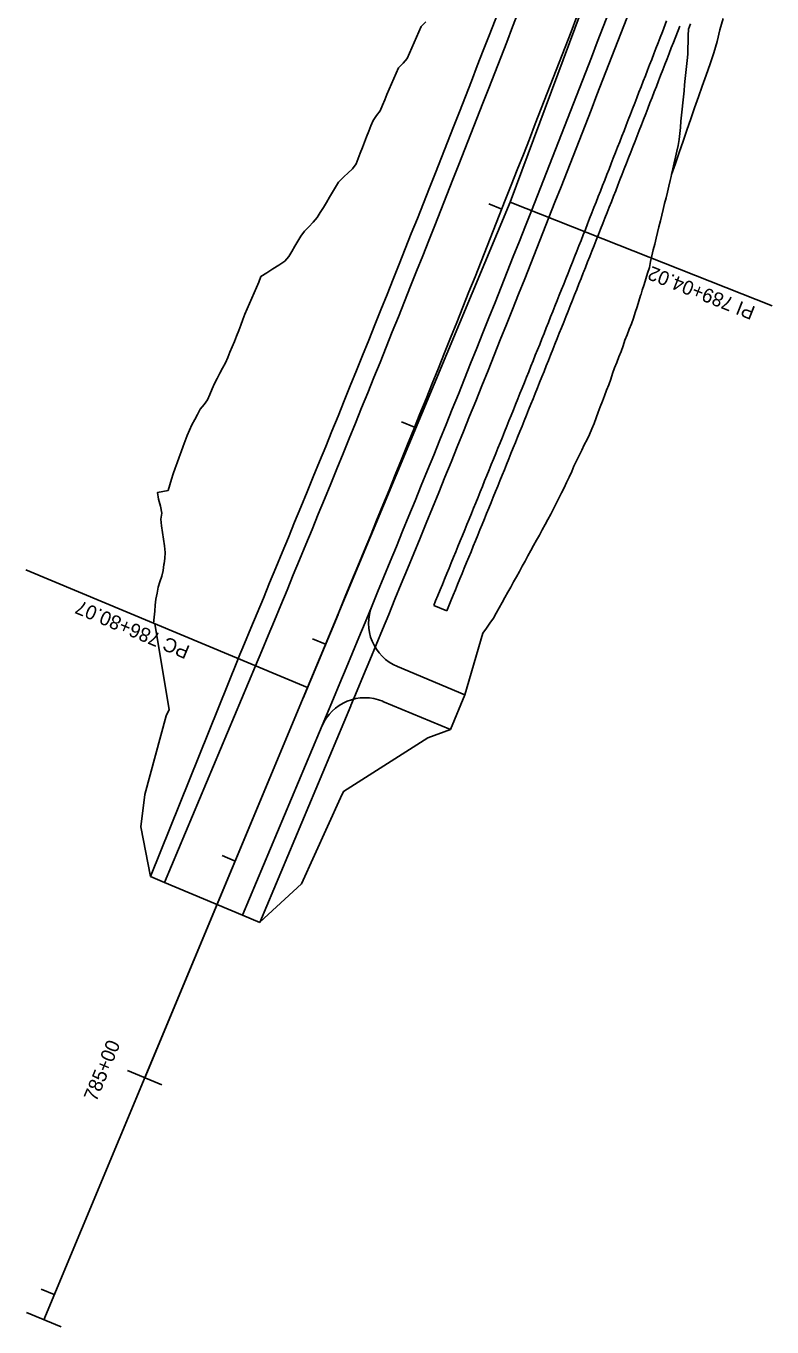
# Model space of a CAD drawing. Extents: x 1237212 to 1293764, y 379349 to 410301.
# Drawn here: x 1282908 to 1283226, y 402702 to 403256 of the extents above; entities that cross this region are included whole.
import ezdxf

# ---------------------------------------------------------------- set-up
doc = ezdxf.new("R2010")
doc.units = 0
for name, color, linetype in [('B-Sub-Footing', 7, 'Continuous'), ('B-Sub-Pier Cap', 7, 'Continuous'), ('B-Tbl-Title Block', 7, 'Continuous'), ('B-Title Block (No Plot)', 7, 'Continuous'), ('R_Exist Surface', 7, 'Continuous'), ('R_Grid', 7, 'Continuous'), ('R_Grid Annot', 7, 'Continuous'), ('R_Shld', 7, 'Continuous')]:
    doc.layers.add(name, color=color, linetype=linetype)

msp = doc.modelspace()

# ---------------------------------------------------------------- linework, layer by layer
at = {"layer": 'B-Sub-Footing'}
for p, q in [((1283066.22, 402983.18), (1283094.95, 402971.22)), ((1283038.94, 402969.6), (1283038.97, 402969.66)), ((1283060.05, 402968.41), (1283088.81, 402956.45)), ((1283094.95, 402971.22), (1283088.81, 402956.45))]:
    msp.add_line(p, q, dxfattribs=at)
for centre, start, end in [((1283073.91, 403001.64), 157.5476, 247.408), ((1283052.37, 402949.95), 67.408, 157.1925)]:
    msp.add_arc(centre, 20, start, end, dxfattribs=at)
at = {"layer": 'B-Sub-Pier Cap'}
for points in [[(1283180.92, 403258.23), (1283179.09, 403253.47), (1283178.19, 403251.13), (1283177.28, 403248.79), (1283176.38, 403246.45), (1283175.48, 403244.12), (1283174.57, 403241.78), (1283173.67, 403239.44), (1283172.76, 403237.1), (1283171.85, 403234.76), (1283170.95, 403232.42), (1283170.04, 403230.08), (1283169.13, 403227.75), (1283168.22, 403225.41), (1283167.31, 403223.07), (1283166.4, 403220.73), (1283165.5, 403218.4), (1283164.58, 403216.06), (1283163.67, 403213.72), (1283162.76, 403211.39), (1283161.85, 403209.05), (1283160.94, 403206.72), (1283160.03, 403204.38), (1283159.11, 403202.04), (1283158.2, 403199.71), (1283157.28, 403197.37), (1283156.37, 403195.04), (1283155.45, 403192.7), (1283154.54, 403190.37), (1283153.62, 403188.03), (1283152.7, 403185.7), (1283151.79, 403183.37), (1283150.87, 403181.03), (1283149.95, 403178.7), (1283149.03, 403176.36), (1283148.11, 403174.03), (1283147.19, 403171.7), (1283146.27, 403169.37), (1283145.35, 403167.03), (1283144.43, 403164.7), (1283143.5, 403162.37), (1283142.58, 403160.04), (1283141.66, 403157.7), (1283140.74, 403155.37), (1283140.05, 403153.64), (1283139.81, 403153.04), (1283138.89, 403150.71), (1283137.96, 403148.38), (1283137.04, 403146.05), (1283136.11, 403143.72), (1283135.18, 403141.39), (1283134.26, 403139.06), (1283133.33, 403136.73), (1283132.4, 403134.4), (1283131.47, 403132.07), (1283130.54, 403129.74), (1283129.61, 403127.41), (1283128.68, 403125.08), (1283127.75, 403122.75), (1283126.82, 403120.42), (1283125.89, 403118.09), (1283124.96, 403115.77), (1283124.02, 403113.44), (1283123.09, 403111.11), (1283122.16, 403108.78), (1283121.22, 403106.46), (1283120.29, 403104.13), (1283119.35, 403101.8), (1283118.42, 403099.47), (1283117.48, 403097.15), (1283116.54, 403094.82), (1283115.61, 403092.5), (1283114.67, 403090.17), (1283113.73, 403087.84), (1283112.79, 403085.52), (1283111.85, 403083.19), (1283110.91, 403080.87), (1283109.97, 403078.54), (1283109.03, 403076.22), (1283108.09, 403073.89), (1283107.15, 403071.57), (1283106.2, 403069.24), (1283105.26, 403066.92), (1283104.32, 403064.6), (1283103.37, 403062.27), (1283102.43, 403059.95), (1283101.48, 403057.63), (1283100.54, 403055.3), (1283099.59, 403052.98), (1283098.65, 403050.66), (1283097.7, 403048.34), (1283096.75, 403046.02), (1283095.8, 403043.69), (1283094.86, 403041.37), (1283093.91, 403039.05), (1283092.96, 403036.73), (1283092.01, 403034.41), (1283091.06, 403032.09), (1283090.11, 403029.77), (1283089.15, 403027.45), (1283088.2, 403025.13), (1283087.25, 403022.81), (1283086.3, 403020.49), (1283085.34, 403018.17), (1283084.39, 403015.85), (1283083.43, 403013.53), (1283082.48, 403011.21), (1283081.67, 403009.25)], [(1283087.21, 403006.94), (1283088.98, 403011.24), (1283089.94, 403013.56), (1283090.89, 403015.88), (1283091.85, 403018.21), (1283092.8, 403020.53), (1283093.75, 403022.85), (1283094.7, 403025.17), (1283095.66, 403027.49), (1283096.61, 403029.81), (1283097.56, 403032.13), (1283098.51, 403034.46), (1283099.46, 403036.78), (1283100.41, 403039.1), (1283101.36, 403041.42), (1283102.31, 403043.75), (1283103.25, 403046.07), (1283104.2, 403048.39), (1283105.15, 403050.72), (1283106.1, 403053.04), (1283107.04, 403055.37), (1283107.99, 403057.69), (1283108.93, 403060.01), (1283109.88, 403062.34), (1283110.82, 403064.66), (1283111.76, 403066.99), (1283112.71, 403069.31), (1283113.65, 403071.64), (1283114.59, 403073.97), (1283115.53, 403076.29), (1283116.47, 403078.62), (1283117.41, 403080.94), (1283118.35, 403083.27), (1283119.29, 403085.6), (1283120.23, 403087.92), (1283121.17, 403090.25), (1283122.11, 403092.58), (1283123.05, 403094.91), (1283123.98, 403097.23), (1283124.92, 403099.56), (1283125.85, 403101.89), (1283126.79, 403104.22), (1283127.72, 403106.55), (1283128.66, 403108.88), (1283129.59, 403111.21), (1283130.53, 403113.53), (1283131.46, 403115.86), (1283132.39, 403118.19), (1283133.32, 403120.52), (1283134.25, 403122.85), (1283135.18, 403125.18), (1283136.11, 403127.51), (1283137.04, 403129.84), (1283137.97, 403132.18), (1283138.9, 403134.51), (1283139.83, 403136.84), (1283140.76, 403139.17), (1283141.69, 403141.5), (1283142.61, 403143.83), (1283143.54, 403146.17), (1283144.46, 403148.5), (1283145.39, 403150.83), (1283145.63, 403151.43), (1283146.31, 403153.16), (1283147.24, 403155.5), (1283148.16, 403157.83), (1283149.08, 403160.16), (1283150.01, 403162.5), (1283150.93, 403164.83), (1283151.85, 403167.16), (1283152.77, 403169.5), (1283153.69, 403171.83), (1283154.61, 403174.17), (1283155.53, 403176.5), (1283156.45, 403178.83), (1283157.37, 403181.17), (1283158.29, 403183.51), (1283159.2, 403185.84), (1283160.12, 403188.18), (1283161.04, 403190.51), (1283161.95, 403192.85), (1283162.87, 403195.18), (1283163.78, 403197.52), (1283164.7, 403199.86), (1283165.61, 403202.19), (1283166.53, 403204.53), (1283167.44, 403206.87), (1283168.35, 403209.21), (1283169.26, 403211.54), (1283170.18, 403213.88), (1283171.09, 403216.22), (1283172, 403218.56), (1283172.91, 403220.9), (1283173.82, 403223.24), (1283174.72, 403225.57), (1283175.63, 403227.91), (1283176.54, 403230.25), (1283177.45, 403232.59), (1283178.35, 403234.93), (1283179.26, 403237.27), (1283180.17, 403239.61), (1283181.07, 403241.95), (1283181.98, 403244.29), (1283182.88, 403246.63), (1283183.78, 403248.97), (1283186.48, 403255.97)], [(1283081.67, 403009.25), (1283087.21, 403006.94)]]:
    msp.add_lwpolyline(points, dxfattribs=at)
at = {"layer": 'B-Tbl-Title Block'}
for p, q in [((1283005.72, 402983.47), (1282966.94, 402891.3)), ((1283005.72, 402983.47), (1283005.75, 402983.54)), ((1283038.94, 402969.6), (1283000.18, 402877.42)), ((1282966.94, 402891.3), (1283000.18, 402877.42))]:
    msp.add_line(p, q, dxfattribs=at)
for radius in [11435.16, 11471.16]:
    msp.add_arc((1272453.81, 407390.3), radius, 337.333333, 339.572534, dxfattribs=at)
at = {"layer": 'B-Title Block (No Plot)'}
for p, q in [((1283026.01, 402969.79), (1283040.89, 403005.4)), ((1282915.47, 402705.09), (1283027.89, 402974.29)), ((1282958.5, 402808.13), (1283027.89, 402974.29))]:
    msp.add_line(p, q, dxfattribs=at)
msp.add_arc((1272453.81, 407390.3), 11459.16, 337.333333, 339.572534, dxfattribs=at)
msp.add_arc((1272453.81, 407390.3), 11459.16, 337.333333, 339.572534, dxfattribs=at)
at = {"layer": 'R_Exist Surface'}
for points in [[(1282962.27, 403001.62), (1282962.52, 403004.21), (1282962.76, 403006.8), (1282963.01, 403009.39), (1282963.3, 403011.96), (1282963.76, 403014.46), (1282964.22, 403016.96), (1282965.03, 403019.31), (1282965.88, 403021.65), (1282966.37, 403024.13), (1282966.7, 403026.68), (1282966.76, 403027.1), (1282967.04, 403029.23), (1282967.25, 403031.83), (1282966.93, 403034.65), (1282966.53, 403037.5), (1282966.13, 403040.36), (1282965.73, 403043.21), (1282965.38, 403046.03), (1282965.8, 403048.55), (1282965.24, 403051.46), (1282964.44, 403054.48), (1282963.98, 403057.35), (1282968.46, 403058.19), (1282969.19, 403060.57), (1282969.91, 403062.95), (1282970.64, 403065.34), (1282971.44, 403067.69), (1282972.3, 403070.02), (1282973.16, 403072.35), (1282974.02, 403074.68), (1282974.88, 403077.01), (1282975.73, 403079.34), (1282976.64, 403081.65), (1282977.61, 403083.93), (1282978.62, 403086.2), (1282979.81, 403088.39), (1282981, 403090.58), (1282982.19, 403092.78), (1282983.88, 403094.77), (1282985.34, 403096.85), (1282986.32, 403099.13), (1282987.3, 403101.41), (1282988.27, 403103.69), (1282989.34, 403105.94), (1282990.53, 403108.13), (1282991.72, 403110.33), (1282992.91, 403112.52), (1282993.88, 403114.81), (1282994.83, 403117.1), (1282995.78, 403119.39), (1282996.74, 403121.68), (1282997.69, 403123.97), (1282998.6, 403126.28), (1282999.45, 403128.62), (1283000.3, 403130.95), (1283001.22, 403133.25), (1283002.2, 403135.53), (1283003.19, 403137.81), (1283004.18, 403140.09), (1283005.17, 403142.36), (1283006.16, 403144.64), (1283007.12, 403146.93), (1283008.03, 403149.24), (1283010.58, 403150.89), (1283013.13, 403152.54), (1283015.68, 403154.19), (1283018.24, 403155.84), (1283019.91, 403157.84), (1283021.2, 403160), (1283022.48, 403162.16), (1283023.77, 403164.32), (1283025.06, 403166.48), (1283026.55, 403168.56), (1283028.41, 403170.49), (1283030.28, 403172.42), (1283032.05, 403174.39), (1283033.34, 403176.55), (1283034.64, 403178.71), (1283035.93, 403180.87), (1283037.24, 403183.02), (1283038.54, 403185.18), (1283039.85, 403187.33), (1283041.15, 403189.49), (1283043.05, 403191.41), (1283043.56, 403191.9), (1283045.05, 403193.29), (1283047.05, 403195.17), (1283048.58, 403197.24), (1283049.48, 403199.56), (1283050.37, 403201.88), (1283051.27, 403204.19), (1283052.18, 403206.51), (1283053.08, 403208.83), (1283053.99, 403211.14), (1283054.89, 403213.45), (1283055.8, 403215.77), (1283057.33, 403217.84), (1283058.86, 403219.91), (1283059.82, 403222.2), (1283060.78, 403224.5), (1283061.74, 403226.79), (1283062.7, 403229.08), (1283063.67, 403231.38), (1283064.63, 403233.67), (1283065.6, 403235.96), (1283066.62, 403238.23), (1283068.59, 403240.13), (1283070.38, 403242.1), (1283071.35, 403244.39), (1283072.33, 403246.68), (1283073.3, 403248.97), (1283074.28, 403251.25), (1283075.26, 403253.54), (1283076.35, 403255.79), (1283078.24, 403257.72)], [(1283182.78, 403191.95), (1283183.04, 403192.69), (1283184.67, 403197.43), (1283186.27, 403202.17), (1283187.91, 403206.91), (1283189.53, 403211.65), (1283191.16, 403216.39), (1283192.8, 403221.12), (1283194.42, 403225.86), (1283196.09, 403230.35), (1283197.81, 403235.05), (1283199.41, 403239.8), (1283200.96, 403244.58), (1283202.41, 403249.39), (1283203.61, 403254.31), (1283204.95, 403259.17)], [(1283191.05, 403256.93), (1283190.19, 403254.57), (1283190.13, 403251.91), (1283190.04, 403249.25), (1283189.92, 403246.6), (1283189.94, 403243.91), (1283189.72, 403241.3), (1283189.43, 403238.72), (1283189.14, 403236.14), (1283188.86, 403233.55), (1283188.59, 403230.96), (1283188.32, 403228.38), (1283188.04, 403225.79), (1283187.77, 403223.2), (1283187.52, 403220.6), (1283187.27, 403218), (1283187.03, 403215.4), (1283186.78, 403212.8), (1283186.54, 403210.2), (1283186.31, 403207.59), (1283185.85, 403205.08), (1283185.26, 403202.61), (1283184.68, 403200.14), (1283184.11, 403197.66), (1283183.54, 403195.19), (1283182.96, 403192.71)], [(1283094.95, 402971.22), (1283102.62, 402997.47), (1283104.11, 402999.58), (1283105.59, 403001.69), (1283107.07, 403003.79), (1283108.31, 403006), (1283109.53, 403008.22), (1283110.77, 403010.43), (1283112.01, 403012.64), (1283113.24, 403014.85), (1283114.48, 403017.06), (1283115.72, 403019.27), (1283116.95, 403021.48), (1283118.19, 403023.69), (1283119.42, 403025.9), (1283120.59, 403028.14), (1283121.77, 403030.37), (1283122.99, 403032.59), (1283124.22, 403034.8), (1283125.45, 403037.02), (1283126.67, 403039.23), (1283127.9, 403041.45), (1283129.12, 403043.67), (1283130.34, 403045.88), (1283131.56, 403048.1), (1283132.69, 403050.36), (1283133.82, 403052.61), (1283134.94, 403054.87), (1283136.06, 403057.13), (1283137.19, 403059.39), (1283138.31, 403061.65), (1283139.44, 403063.91), (1283140.45, 403066.21), (1283141.37, 403068.55), (1283142.45, 403070.83), (1283143.58, 403073.08), (1283144.71, 403075.34), (1283145.84, 403077.59), (1283146.98, 403079.85), (1283148.11, 403082.1), (1283149.06, 403084.43), (1283149.98, 403086.77), (1283150.87, 403089.13), (1283151.76, 403091.48), (1283152.66, 403093.83), (1283153.55, 403096.18), (1283154.44, 403098.54), (1283155.34, 403100.89), (1283156.24, 403103.24), (1283157.13, 403105.59), (1283157.9, 403107.99), (1283158.76, 403110.35), (1283159.67, 403112.7), (1283160.58, 403115.04), (1283161.49, 403117.39), (1283162.33, 403119.76), (1283163.16, 403122.14), (1283164.07, 403124.48), (1283164.99, 403126.82), (1283165.91, 403129.17), (1283166.82, 403131.51), (1283167.56, 403133.92), (1283168.3, 403136.33), (1283169.05, 403138.74), (1283169.8, 403141.15), (1283170, 403141.77), (1283170.55, 403143.56), (1283171.31, 403145.96), (1283172.06, 403148.37), (1283172.81, 403150.78), (1283173.57, 403153.18), (1283174.08, 403155.69), (1283174.64, 403158.16), (1283175.24, 403160.63), (1283175.84, 403163.1), (1283176.44, 403165.57), (1283177.03, 403168.03), (1283177.64, 403170.5), (1283178.24, 403172.96), (1283178.84, 403175.43), (1283179.44, 403177.89), (1283180.05, 403180.35), (1283180.66, 403182.82), (1283181.26, 403185.28), (1283181.81, 403187.77), (1283182.38, 403190.24), (1283182.78, 403191.95)], [(1282962.88, 403001.36), (1282968.98, 402964.92), (1282967.7, 402962.2), (1282958.51, 402928.73), (1282956.9, 402914.92), (1282960.97, 402893.79)], [(1283088.81, 402956.45), (1283079.18, 402952.8), (1283043.19, 402930.05), (1283041.92, 402927.33), (1283025.26, 402890.75), (1283007.56, 402874.34)]]:
    msp.add_lwpolyline(points, dxfattribs=at)
at = {"layer": 'R_Grid'}
for points in [[(1283027.89, 402974.29), (1283114.2, 403180.94), (1283192.36, 403390.81)], [(1283114.2, 403180.94), (1283225.81, 403136.87)], [(1283114.2, 403180.94), (1283225.81, 403136.87)], [(1283027.89, 402974.29), (1282907.93, 403024.39)], [(1283027.89, 402974.29), (1282907.93, 403024.39)]]:
    msp.add_lwpolyline(points, dxfattribs=at)
at = {"layer": 'R_Grid Annot'}
for points in [[(1283105.11, 403180.24), (1283110.69, 403178.03)], [(1283105.11, 403180.24), (1283110.69, 403178.03)], [(1283067.97, 403087.45), (1283073.53, 403085.2)], [(1283067.97, 403087.45), (1283073.53, 403085.2)], [(1283030.02, 402994.99), (1283035.56, 402992.69)], [(1283030.02, 402994.99), (1283035.56, 402992.69)], [(1282991.5, 402902.72), (1282997.04, 402900.4)], [(1282991.5, 402902.72), (1282997.04, 402900.4)], [(1282951.12, 402811.21), (1282965.88, 402805.05)], [(1282951.12, 402811.21), (1282965.88, 402805.05)], [(1282914.43, 402718.16), (1282919.96, 402715.85)], [(1282908.09, 402708.17), (1282922.85, 402702.01)], [(1282908.09, 402708.17), (1282922.85, 402702.01)]]:
    msp.add_lwpolyline(points, dxfattribs=at)
at = {"layer": 'R_Shld'}
for p, q in [((1282998.34, 402986.56), (1282960.97, 402893.79)), ((1282998.34, 402986.56), (1282998.36, 402986.62)), ((1283000.18, 402985.79), (1283000.21, 402985.85)), ((1283046.32, 402966.52), (1283007.64, 402874.3)), ((1283046.32, 402966.52), (1283046.35, 402966.58)), ((1282966.94, 402891.3), (1282960.97, 402893.79)), ((1283000.18, 402877.42), (1283007.64, 402874.3))]:
    msp.add_line(p, q, dxfattribs=at)
for radius in [11427.16, 11479.16]:
    msp.add_arc((1272453.81, 407390.3), radius, 337.333333, 339.572534, dxfattribs=at)

# ---------------------------------------------------------------- texts
at = {"layer": 'R_Grid'}
for s, rotation, p in [('PI 789+04.02', 158.4529, (1283219.13, 403136.28)), ('PI 789+04.02', 158.4529, (1283219.13, 403136.28)), ('PC 786+80.07', 157.3333, (1282978.2, 402991.79)), ('PC 786+80.07', 157.3333, (1282978.2, 402991.79))]:
    msp.add_text(s, height=6, rotation=rotation, dxfattribs=at).set_placement(p)
at = {"layer": 'R_Grid Annot'}
msp.add_text('785+00', height=6, rotation=67.3333, dxfattribs=at).set_placement((1282937.86, 402797.63))

doc.saveas('drawing.dxf')
